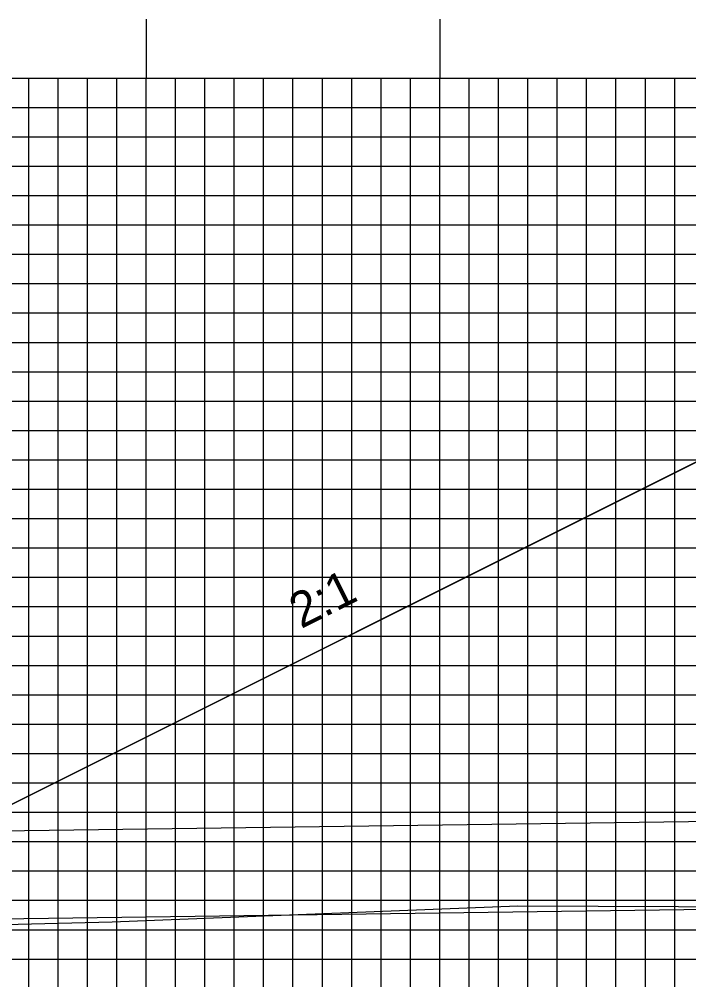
# Model space of a CAD drawing. Extents: x 1789337 to 1789680, y 442591 to 442811.
# Drawn here: x 1789448.35 to 1789471.15, y 442672.96 to 442705.67 of the extents above; entities that cross this region are included whole.
import ezdxf

# ---------------------------------------------------------------- set-up
doc = ezdxf.new("R2010")
doc.units = 0
for name, color, linetype in [('ANNOTATION', 7, 'Continuous'), ('D_Drainage_Culvert', 7, 'Continuous'), ('D_Roadway_Centerline', 7, 'Continuous'), ('D_Roadway_SlopeLines', 7, 'Continuous'), ('MAJOR', 7, 'Continuous'), ('MINOR', 7, 'Continuous'), ('S_Roadway_Centerline', 7, 'Continuous')]:
    doc.layers.add(name, color=color, linetype=linetype)

msp = doc.modelspace()

# ---------------------------------------------------------------- linework, layer by layer
at = {"layer": 'D_Drainage_Culvert'}
msp.add_lwpolyline([(1789436.847, 442674.881), (1789436.806, 442677.881), (1789580.792, 442679.841), (1789580.833, 442676.842)], close=True, dxfattribs=at)
at = {"layer": 'D_Roadway_Centerline'}
msp.add_lwpolyline([(1789439.928, 442674.854), (1789474.92, 442692.35), (1789479.67, 442694.725), (1789482.67, 442694.845), (1789490.67, 442695.165), (1789502.67, 442695.405), (1789514.67, 442695.547), (1789522.67, 442695.227), (1789525.67, 442695.107), (1789532.946, 442692.682), (1789569.184, 442680.602)], dxfattribs=at)
at = {"layer": 'D_Roadway_SlopeLines'}
msp.add_lwpolyline([(1789479.67, 442694.725), (1789439.928, 442674.854)], dxfattribs=at)
at = {"layer": 'MAJOR'}
for p, q in [((1789452.67, 442705.669), (1789452.67, 442703.665)), ((1789462.67, 442705.669), (1789462.67, 442703.665)), ((1789362.67, 442703.665), (1789642.67, 442703.665)), ((1789362.67, 442703.665), (1789642.67, 442703.665)), ((1789452.67, 442668.665), (1789452.67, 442703.665)), ((1789462.67, 442668.665), (1789462.67, 442703.665)), ((1789362.67, 442698.665), (1789642.67, 442698.665)), ((1789362.67, 442693.665), (1789642.67, 442693.665)), ((1789362.67, 442688.665), (1789642.67, 442688.665)), ((1789362.67, 442683.665), (1789642.67, 442683.665)), ((1789362.67, 442678.665), (1789642.67, 442678.665)), ((1789362.67, 442673.665), (1789642.67, 442673.665))]:
    msp.add_line(p, q, dxfattribs=at)
at = {"layer": 'MINOR'}
for p, q in [((1789448.67, 442668.665), (1789448.67, 442703.665)), ((1789449.67, 442668.665), (1789449.67, 442703.665)), ((1789450.67, 442668.665), (1789450.67, 442703.665)), ((1789451.67, 442668.665), (1789451.67, 442703.665)), ((1789453.67, 442668.665), (1789453.67, 442703.665)), ((1789454.67, 442668.665), (1789454.67, 442703.665)), ((1789455.67, 442668.665), (1789455.67, 442703.665)), ((1789456.67, 442668.665), (1789456.67, 442703.665)), ((1789457.67, 442668.665), (1789457.67, 442703.665)), ((1789458.67, 442668.665), (1789458.67, 442703.665)), ((1789459.67, 442668.665), (1789459.67, 442703.665)), ((1789460.67, 442668.665), (1789460.67, 442703.665)), ((1789461.67, 442668.665), (1789461.67, 442703.665)), ((1789463.67, 442668.665), (1789463.67, 442703.665)), ((1789464.67, 442668.665), (1789464.67, 442703.665)), ((1789465.67, 442668.665), (1789465.67, 442703.665)), ((1789466.67, 442668.665), (1789466.67, 442703.665)), ((1789467.67, 442668.665), (1789467.67, 442703.665)), ((1789468.67, 442668.665), (1789468.67, 442703.665)), ((1789469.67, 442668.665), (1789469.67, 442703.665)), ((1789470.67, 442668.665), (1789470.67, 442703.665)), ((1789362.67, 442702.665), (1789642.67, 442702.665)), ((1789362.67, 442701.665), (1789642.67, 442701.665)), ((1789362.67, 442700.665), (1789642.67, 442700.665)), ((1789362.67, 442699.665), (1789642.67, 442699.665)), ((1789362.67, 442697.665), (1789642.67, 442697.665)), ((1789362.67, 442696.665), (1789642.67, 442696.665)), ((1789362.67, 442695.665), (1789642.67, 442695.665)), ((1789362.67, 442694.665), (1789642.67, 442694.665)), ((1789362.67, 442692.665), (1789642.67, 442692.665)), ((1789362.67, 442691.665), (1789642.67, 442691.665)), ((1789362.67, 442690.665), (1789642.67, 442690.665)), ((1789362.67, 442689.665), (1789642.67, 442689.665)), ((1789362.67, 442687.665), (1789642.67, 442687.665)), ((1789362.67, 442686.665), (1789642.67, 442686.665)), ((1789362.67, 442685.665), (1789642.67, 442685.665)), ((1789362.67, 442684.665), (1789642.67, 442684.665)), ((1789362.67, 442682.665), (1789642.67, 442682.665)), ((1789362.67, 442681.665), (1789642.67, 442681.665)), ((1789362.67, 442680.665), (1789642.67, 442680.665)), ((1789362.67, 442679.665), (1789642.67, 442679.665)), ((1789362.67, 442677.665), (1789642.67, 442677.665)), ((1789362.67, 442676.665), (1789642.67, 442676.665)), ((1789362.67, 442675.665), (1789642.67, 442675.665)), ((1789362.67, 442674.665), (1789642.67, 442674.665))]:
    msp.add_line(p, q, dxfattribs=at)
at = {"layer": 'S_Roadway_Centerline'}
msp.add_lwpolyline([(1789411.113, 442674.678), (1789421.04, 442674.707), (1789429.721, 442674.879), (1789433.263, 442674.912), (1789442.071, 442674.836), (1789445.873, 442674.801), (1789447.377, 442674.827), (1789451.513, 442674.93), (1789465.326, 442675.481), (1789478.998, 442675.422), (1789484.619, 442675.469), (1789490.001, 442675.603), (1789502.084, 442675.847), (1789506.444, 442675.953), (1789516.501, 442675.856), (1789519.764, 442675.815), (1789521.08, 442675.832), (1789524.932, 442675.953), (1789538.491, 442676.422), (1789543.71, 442676.424), (1789556.808, 442676.443), (1789556.809, 442676.443), (1789575.02, 442676.753)], dxfattribs=at)

# ---------------------------------------------------------------- texts
at = {"layer": 'ANNOTATION'}
msp.add_text('2:1', height=1.2, rotation=26.5651, dxfattribs=at).set_placement((1789457.944, 442684.899))

doc.saveas('drawing.dxf')
